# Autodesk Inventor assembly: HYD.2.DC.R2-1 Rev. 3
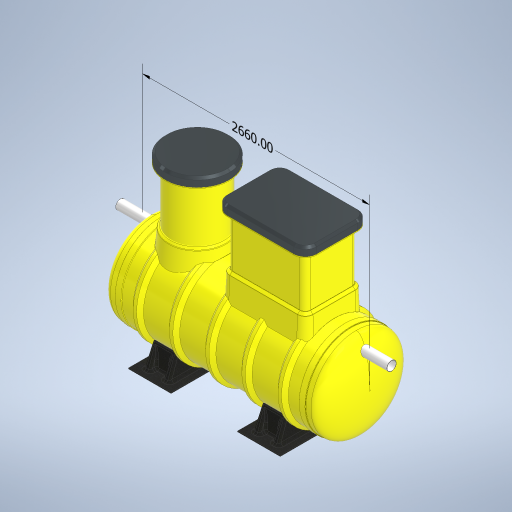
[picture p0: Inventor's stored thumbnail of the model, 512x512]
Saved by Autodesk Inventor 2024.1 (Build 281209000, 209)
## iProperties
Created: 2023-10
Part Number: HYD.2.DC.R2-1 Rev. 3
Document SubType Name: Assembly
Designer: macga
Author: macga
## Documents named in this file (42)
- D:\$ Protector Vault\Workspace\Automation Files\1. Protector Stardard Products\HydroProtectors\FAMILY\HYD.2 - Vernon\HYD.2.DC.R2-1 Rev. 3.iam
- D:\$ Protector Vault\Workspace\1. Protector Stardard Products\HydroProtectors\FAMILY\HORIZONTAL TANK - IPART\HORIZONTAL TANK - IPART.ipt
- D:\$ Protector Vault\Workspace\1. Protector Stardard Products\HydroProtectors\FAMILY\DOME - IPART\DOME - IPART.ipt
- D:\$ Protector Vault\Workspace\1. Protector Stardard Products\HydroProtectors\FAMILY\ACDTUBE - IPART\ACDTUBE - IPART.ipt
- D:\$ Protector Vault\Workspace\1. Protector Stardard Products\HydroProtectors\FAMILY\ACD FLOAT VALVE - IPART\ACD.FloatValve - IASSY\ACD.FVALVE.225.ASSY.iam
- D:\$ Protector Vault\Workspace\1. Protector Stardard Products\HydroProtectors\FAMILY\ACD FLOAT VALVE - IPART\ACD.FloatValve - IASSY.iam
- D:\$ Protector Vault\Workspace\1. Protector Stardard Products\HydroProtectors\FAMILY\SU.600Dia Manway Adaptor - IPART\SU.MWA.HS.6R - IPART.ipt
- D:\$ Protector Vault\Workspace\1. Protector Stardard Products\HydroProtectors\FAMILY\600x900mm Manway Adaptor - IPART\600x900mm Manway Adaptor - IPART.ipt
- D:\$ Protector Vault\Workspace\1. Protector Stardard Products\HydroProtectors\Coalescer Guide Rail.ipt
- D:\$ Protector Vault\Workspace\1. Protector Stardard Products\Standard Components\600mm Riser.ipt
- D:\$ Protector Vault\Workspace\1. Protector Stardard Products\Standard Components\600x900 - 600mm Manway Riser.ipt
- D:\$ Protector Vault\Workspace\1. Protector Stardard Products\Standard Components\Flanged Vent.ipt
- D:\$ Protector Vault\Workspace\1. Protector Stardard Products\HydroProtectors\Upper Guide Rai Braket.ipt
- D:\$ Protector Vault\Workspace\1. Protector Stardard Products\Xtremeprotector\Vault\Lifting Eye.ipt
- D:\$ Protector Vault\Workspace\1. Protector Stardard Products\Xtremeprotector\Vault\Chain.ipt
- D:\$ Protector Vault\Workspace\1. Protector Stardard Products\Standard Components\600mm Cast Iron Cover ST\600mm Cass D Cover-01.ipt
- D:\$ Protector Vault\Workspace\1. Protector Stardard Products\Standard Components\600mm Cast Iron Cover ST.ipt
- D:\$ Protector Vault\Workspace\Automation Files\600x900mm Manway Cover ST B and D\600x900mm Manway Cover-D.ipt
- D:\$ Protector Vault\Workspace\Automation Files\600x900mm Manway Cover ST B and D.ipt
- D:\$ Protector Vault\Workspace\1. Protector Stardard Products\HydroProtectors\FAMILY\INLET PIPE ELBOW- IPART\INLET PIPE ELBOW- IPART.ipt
- D:\$ Protector Vault\Workspace\1. Protector Stardard Products\HydroProtectors\HYD Oil Probe\Oil Probe Assembly.iam
- D:\$ Protector Vault\Workspace\1. Protector Stardard Products\HydroProtectors\FAMILY\FOOT - IPART\FRP Foot - IPART.ipt
- D:\$ Protector Vault\Workspace\1. Protector Stardard Products\HydroProtectors\FAMILY\COALESCER FILTER - IPART\CF-R2.iam
- D:\$ Protector Vault\Workspace\1. Protector Stardard Products\HydroProtectors\FAMILY\DOME - IPART\DOME - IPART\SU.DOME.1050-6.ipt
- D:\$ Protector Vault\Workspace\1. Protector Stardard Products\HydroProtectors\FAMILY\HYD.BAFFLE - IPART\SU.BAFFLE.1050\SU.BAFFLE.1050.ipt
- D:\$ Protector Vault\Workspace\1. Protector Stardard Products\HydroProtectors\FAMILY\HYD.BAFFLE - IPART\SU.BAFFLE.1050.ipt
- D:\$ Protector Vault\Workspace\1. Protector Stardard Products\HydroProtectors\FAMILY\ACD Base - IPART\SU.ACDBASE.1050\SU.ACDBASE.1050.ipt
- D:\$ Protector Vault\Workspace\1. Protector Stardard Products\HydroProtectors\FAMILY\ACD Base - IPART\SU.ACDBASE.1050.ipt
- D:\$ Protector Vault\Workspace\1. Protector Stardard Products\HydroProtectors\FAMILY\CF.BASE - IPART\CF BASE SINGLE - IPART\SU.CFBASE.1050\SU.CFBASE.1050.ipt
- D:\$ Protector Vault\Workspace\1. Protector Stardard Products\HydroProtectors\FAMILY\CF.BASE - IPART\CF BASE SINGLE - IPART\SU.CFBASE.1050.ipt
- D:\$ Protector Vault\Workspace\1. Protector Stardard Products\HydroProtectors\FAMILY\FOOT - IPART\FRP Foot - IPART\SU.HS.FOOT.1050.ipt
- D:\$ Protector Vault\Workspace\1. Protector Stardard Products\HydroProtectors\FAMILY\600x900mm Manway Adaptor - IPART\600x900mm Manway Adaptor - IPART\SU.MRADAPTOR.1050.600Lx900W.ipt
- D:\$ Protector Vault\Workspace\1. Protector Stardard Products\HydroProtectors\FAMILY\SU.600Dia Manway Adaptor - IPART\Horizontal 600mmDia Manway Adaptor (FLANGED) SU.MWA.HS.6R-1850-1850\SU.MWA.HS.6R-1050.ipt
- D:\$ Protector Vault\Workspace\1. Protector Stardard Products\HydroProtectors\FAMILY\ACDTUBE - IPART\ACDTUBE - IPART\ACDTUBE.225-1100.ipt
- D:\$ Protector Vault\Workspace\Automation Files\1. Protector Stardard Products\HydroProtectors\FAMILY\CF.BASE - IPART\Moulds\Coalescer Guide Rail-0122.ipt
- D:\$ Protector Vault\Workspace\1. Protector Stardard Products\Xtremeprotector\Vault\Chain\Chain-26.ipt
- D:\$ Protector Vault\Workspace\1. Protector Stardard Products\HydroProtectors\FAMILY\INLET PIPE ELBOW- IPART\INLET PIPE ELBOW- IPART\InletPipeElbow.100D.ipt
- D:\$ Protector Vault\Workspace\1. Protector Stardard Products\Xtremeprotector\Vault\ISO 4065 Pipe DN110x2.1xS26.7 - 1500.ipt
- D:\$ Protector Vault\Workspace\1. Protector Stardard Products\HydroProtectors\FAMILY\HORIZONTAL TANK - IPART\HORIZONTAL TANK - IPART\WIN.HB.1050x2220L-6.ipt
- D:\$ Protector Vault\Workspace\1. Protector Stardard Products\HydroProtectors\FAMILY\OUTLET ELBOW - IPART\T- ELBOW - IPART\T-Elbow.100D.ipt
- D:\$ Protector Vault\Workspace\1. Protector Stardard Products\HydroProtectors\FAMILY\OUTLET ELBOW - IPART\T- ELBOW - IPART.ipt
- D:\$ Protector Vault\Workspace\1. Protector Stardard Products\Trade Waste Sampling Point Assembly.iam
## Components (30 placed, 25 different names)
1. WIN.HB.1050x2220L-6:1
2. SU.DOME.1050-6:1 — Mate:3, Mate:4, Angle:7, Mate:6
3. SU.DOME.1050-6:2 — Mate:1, Mate:5, Angle:8
4. SU.BAFFLE.1050:1 — Mate:6
5. SU.ACDBASE.1050:1 — Mate:7
6. ACDTUBE.225-1100:1 — Angle:11, Mate:11, Mate:22
7. ACD.FVALVE.225.ASSY:1 [sub-assembly] — Mate:11, Flush:2
8. SU.CFBASE.1050:1
9. SU.MWA.HS.6R-1050:1
10. SU.MRADAPTOR.1050.600Lx900W:1 — Mate:24, Mate:30, Mate:31, Mate:32, Mate:36, Mate:37
11. CF-R2:1 [sub-assembly]
12. Coalescer Guide Rail-0122:1 — Mate:38, Mate:39, Flush:23
13. 600mm Riser:1 — Flush:22, Mate:33, Mate:44, Mate:45, Flush:2
14. 600x900 - 600mm Manway Riser:1
15. Flanged Vent:1 — Mate:34, Mate:35
16. Flanged Vent:2 — Mate:36, Mate:37
17. Upper Guide Rai Braket:1 — Mate:38, Mate:39, Flush:23
18. Lifting Eye:1 — Mate:40, Mate:41, Mate:42, Tangent:3
19. Chain-26:1 — Tangent:3
20. 600mm Cass D Cover-01:1 — Mate:44, Mate:45
21. 600x900mm Manway Cover-D:1 — Mate:46, Flush:24, Flush:25
22. ISO 4065 Pipe DN110x2.1xS26.7 - 1500:1 — Mate:47, Mate:69
23. T-Elbow.100D:1 — Mate:51
24. InletPipeElbow.100D:1 — Mate:55
25. Oil Probe Assembly:1 [sub-assembly] — Mate:58, Flush:57, Angle:17
26. SU.HS.FOOT.1050:1 — Mate:59, Mate:60, Angle:15
27. SU.HS.FOOT.1050:2 — Mate:61, Mate:62, Angle:16
28. ISO 4065 Pipe DN110x2.1xS26.7 - 1500:3 — Mate:70, Mate:71
29. ISO 4065 Pipe DN110x2.1xS26.7 - 1500:2
30. Trade Waste Sampling Point Assembly:1 [sub-assembly] — Mate:70, Mate:71
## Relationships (49: Mate 36, Angle 6, Flush 6, Tangent 1)
- Mate:1: SU.DOME.1050-6:2
- Mate:3: SU.DOME.1050-6:1
- Mate:4: SU.DOME.1050-6:1
- Mate:5: SU.DOME.1050-6:2
- Angle:7: SU.DOME.1050-6:1
- Angle:8: SU.DOME.1050-6:2
- Mate:6: SU.DOME.1050-6:1 ↔ SU.BAFFLE.1050:1
- Mate:7: SU.ACDBASE.1050:1
- Angle:11: ACDTUBE.225-1100:1
- Mate:11: ACDTUBE.225-1100:1 ↔ ACD.FVALVE.225.ASSY:1
- Flush:2: ACD.FVALVE.225.ASSY:1 ↔ 600mm Riser:1
- Mate:22: ACDTUBE.225-1100:1
- Mate:24: SU.MRADAPTOR.1050.600Lx900W:1
- Mate:30: SU.MRADAPTOR.1050.600Lx900W:1
- Mate:31: SU.MRADAPTOR.1050.600Lx900W:1
- Mate:32: SU.MRADAPTOR.1050.600Lx900W:1
- Flush:22: 600mm Riser:1
- Mate:33: 600mm Riser:1
- Mate:34: Flanged Vent:1
- Mate:35: Flanged Vent:1
- Mate:36: SU.MRADAPTOR.1050.600Lx900W:1 ↔ Flanged Vent:2
- Mate:37: SU.MRADAPTOR.1050.600Lx900W:1 ↔ Flanged Vent:2
- Mate:38: Coalescer Guide Rail-0122:1 ↔ Upper Guide Rai Braket:1
- Mate:39: Coalescer Guide Rail-0122:1 ↔ Upper Guide Rai Braket:1
- Flush:23: Coalescer Guide Rail-0122:1 ↔ Upper Guide Rai Braket:1
- Mate:40: Lifting Eye:1
- Mate:41: Lifting Eye:1
- Mate:42: Lifting Eye:1
- Tangent:3: Lifting Eye:1 ↔ Chain-26:1
- Mate:44: 600mm Riser:1 ↔ 600mm Cass D Cover-01:1
- Mate:45: 600mm Riser:1 ↔ 600mm Cass D Cover-01:1
- Mate:46: 600x900mm Manway Cover-D:1
- Flush:24: 600x900mm Manway Cover-D:1
- Flush:25: 600x900mm Manway Cover-D:1
- Mate:47: ISO 4065 Pipe DN110x2.1xS26.7 - 1500:1
- Mate:51: T-Elbow.100D:1
- Mate:55: InletPipeElbow.100D:1
- Mate:58: Oil Probe Assembly:1
- Flush:57: Oil Probe Assembly:1
- Mate:59: SU.HS.FOOT.1050:1
- Mate:60: SU.HS.FOOT.1050:1
- Mate:61: SU.HS.FOOT.1050:2
- Mate:62: SU.HS.FOOT.1050:2
- Angle:15: SU.HS.FOOT.1050:1
- Angle:16: SU.HS.FOOT.1050:2
- Angle:17: Oil Probe Assembly:1
- Mate:69: ISO 4065 Pipe DN110x2.1xS26.7 - 1500:1
- Mate:70: ISO 4065 Pipe DN110x2.1xS26.7 - 1500:3 ↔ Trade Waste Sampling Point Assembly:1
- Mate:71: ISO 4065 Pipe DN110x2.1xS26.7 - 1500:3 ↔ Trade Waste Sampling Point Assembly:1
